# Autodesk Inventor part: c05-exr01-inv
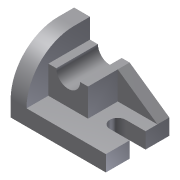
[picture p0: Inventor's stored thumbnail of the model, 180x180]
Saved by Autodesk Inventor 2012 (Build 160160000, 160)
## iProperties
Shininess: 77.0
Length Units: 11269
Angle Units: 11279
Time Units: 11290
Mass Units: 11283
Length Display Precision: 3
Angle Display Precision: 2
Created: 2001-11
Part Number: c05-exr01-inv
Document SubType Name: Modeling
Designer: Renu Muthoo
Density: 1 g/cm^3
Material: Default
Density: 0.0
Volumn: 0.0
Area: 0.0
PropertySet Name: Model Information
Control State: 0
Master: False
Checked Out: False
Author: Renu Muthoo
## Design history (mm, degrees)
sketch "Sketch1"
  geometry: L1 (-48, 36)-(48, 36); L2 (48, -28)-(-48, -28); L3 (-48, -28)-(-48, 36); L4 (48, 12)-(28, 12); L5 (28, -4)-(48, -4); L6 (48, 36)-(48, 12); L7 (48, -4)-(48, -28); A1 r 8 centre (28, 4) between (28, 12) and (28, -4)
  constraints: 14 end point, 4 parallel, 3 perpendicular, 2 point on circle, 2 tangent, 1 centre point, 1 collinear, 1 horizontal
  dimensions: "d0" = 96 distance of L2.start L2.end; "d1" = 64 distance of L2.end L1.start; "d2" = 20 distance of L4.start L4.end; "d3" = 24 distance between parallel lines of L2 L5; "d4" = 16 distance between parallel lines of L4 L5
extrude "Extrusion1" new body sketch "Sketch1" distance "d5" = 16; taper "d6" = 0 deg
sketch "Sketch2"
  geometry: L1 (16, 64)-(64, 64); L2 (64, 64)-(64, 48); L3 (16, 0)-(16, 0); L4 (16, 0)-(16, 64); L5 (0, 64)-(16, 64) reference; L6 (16, 0)-(16, 64) reference; L7 (0, 0)-(16, 0) reference; L8 (0, 0)-(0, 64) reference; A1 r 48 centre (16, 48) between (16, 0) and (64, 48)
  constraints: 8 end point, 3 collinear, 3 perpendicular, 2 point on circle, 2 tangent, 1 centre point, 1 horizontal
  dimensions: "d7" = 64 distance between parallel lines of L2 L8; "d8" = 48 radius of A1
extrude "Extrusion2" join sketch "Sketch2" distance "d9" = 16; taper "d10" = 0 deg
sketch "Sketch3"
  geometry: L1 (16, -44)-(16, -16); L2 (16, -16)-(56, -16); L3 (56, -16)-(56, -44); L4 (56, -44)-(48, -44); L5 (24, -44)-(16, -44); L6 (16, -64)-(16, -16) reference; L7 (16, -16)-(96, -16) reference; A1 r 12 centre (36, -44) between (48, -44) and (24, -44)
  constraints: 10 end point, 3 collinear, 3 parallel, 2 equal length, 2 point on circle, 1 centre point, 1 perpendicular, 1 point on line, 1 vertical
  dimensions: "d11" = 28 distance of L2.end L3.end; "d12" = 8 distance of L3.end L4.end; "d13" = 24 distance of L5.start L4.end
extrude "Extrusion3" join sketch "Sketch3" distance "d14" = 42; taper "d15" = 0 deg
sketch "Sketch4"
  geometry: L1 (56, -16)-(96, -16) reference; L2 (56, -16)-(56, -44) reference; L3 (96, -16)-(56, -44)
  constraints: 2 end point
extrude "Extrusion4" join sketch "Sketch4" distance "d16" = 12; taper "d17" = 0 deg
body "Solid1"
